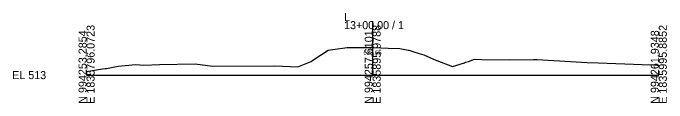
# Model space of a CAD drawing. Extents: x -26 to 2403, y -10 to 9558.
# Drawn here: x -25.7 to 202.8, y -9.7 to 21.6 of the extents above; entities that cross this region are included whole.
import ezdxf

# ---------------------------------------------------------------- set-up
doc = ezdxf.new("R2010")
doc.units = 0
for name, color, linetype in [('Exist Cross Section Cell', 7, 'Continuous'), ('Exist XS Center Line Elevation Label', 7, 'Continuous'), ('Exist XS Ground Line', 7, 'Continuous'), ('Scratch_Level_6', 7, 'Continuous')]:
    doc.layers.add(name, color=color, linetype=linetype)

msp = doc.modelspace()

# ---------------------------------------------------------------- linework, layer by layer
at = {"layer": 'Exist Cross Section Cell'}
for p, q in [((100, 0), (100, 18.81)), ((0, 0), (100, 0)), ((100, 0), (200, 0))]:
    msp.add_line(p, q, dxfattribs=at)
at = {"layer": 'Exist XS Ground Line'}
msp.add_lwpolyline([(0, 1.27), (5.59, 2.13), (6.45, 2.24), (7, 2.35), (11.03, 3.15), (17.16, 3.72), (20.03, 3.5), (25.49, 3.68), (38, 3.87), (44.03, 3.14), (65.78, 3.27), (73.82, 2.92), (78.47, 4.73), (79.13, 5.17), (84.41, 8.66), (86.87, 9.01), (91.09, 9.6), (95.75, 9.65), (100, 9.65), (100.29, 9.65), (105.4, 9.44), (109.53, 9.3), (112.4, 8.73), (112.68, 8.71), (114.04, 8.28), (116.28, 7.53), (117.91, 7.03), (122.32, 5.09), (122.35, 5.07), (122.38, 5.07), (127.92, 3), (132.08, 4.24), (132.46, 4.46), (133.48, 4.76), (135.54, 5.51), (138, 5.39), (147.73, 5.36), (156.17, 5.41), (157.3, 5.41), (157.53, 5.39), (174.98, 4.34), (178.87, 4.24), (194.22, 3.74), (198.73, 3.52), (200, 3.4)], dxfattribs=at)

# ---------------------------------------------------------------- texts
at = {"layer": 'Exist Cross Section Cell'}
for s, p in [('L', (90, 18.81)), ('13+00.00 / 1', (90, 16.01)), ('EL 513', (-26, -1.4))]:
    msp.add_text(s, height=2.8, dxfattribs=at).set_placement(p)
for s, p in [('E 1835796.0723', (2.8, -10)), ('E 1835895.9788', (102.8, -10)), ('E 1835995.8852', (202.8, -10)), ('N 994253.2854', (0, -10)), ('N 994257.6101', (100, -10)), ('N 994261.9348', (200, -10))]:
    msp.add_text(s, height=2.8, rotation=90, dxfattribs=at).set_placement(p)
at = {"layer": 'Exist XS Center Line Elevation Label'}
msp.add_text('522.65', height=1.5, dxfattribs=at).set_placement((96.77, 7.15))
at = {"layer": 'Scratch_Level_6'}
msp.add_text('-', height=0.01, dxfattribs=at).set_placement((0, -0.01))

doc.saveas('drawing.dxf')
